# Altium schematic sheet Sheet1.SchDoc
size A4; SheetNumber: 3; SheetTotal: 4
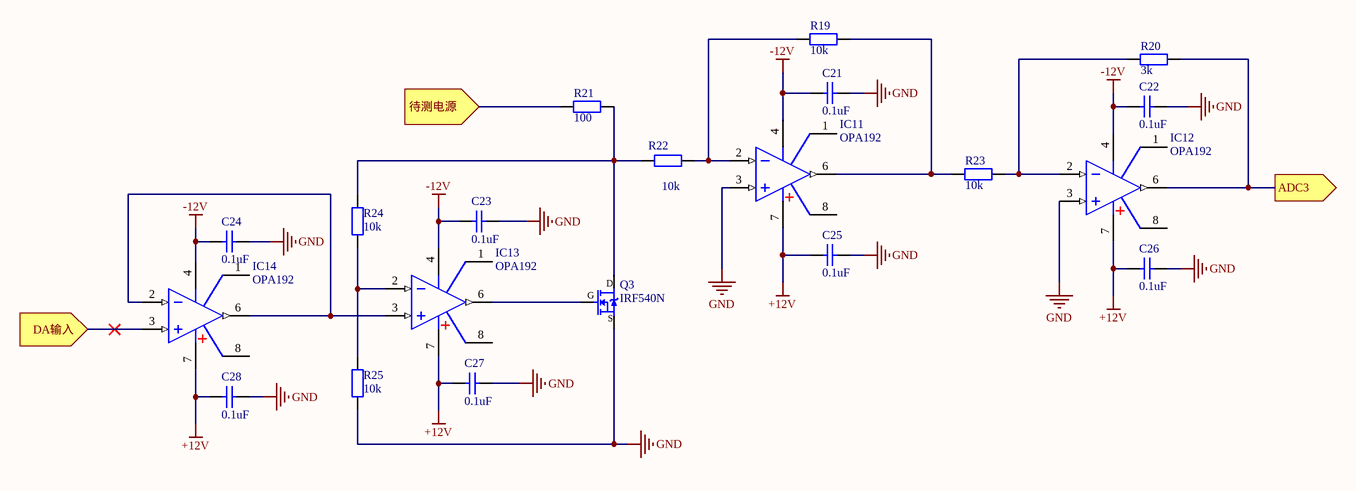
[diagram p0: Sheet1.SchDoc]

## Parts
C21  0.1uF  [瓷片电容]
C22  0.1uF  [瓷片电容]
C23  0.1uF  [瓷片电容]
C24  0.1uF  [瓷片电容]
C25  0.1uF  [瓷片电容]
C26  0.1uF  [瓷片电容]
C27  0.1uF  [瓷片电容]
C28  0.1uF  [瓷片电容]
IC11  OPA192  [SOP8_N]
IC12  OPA192  [SOP8_N]
IC13  OPA192  [SOP8_N]
IC14  OPA192  [SOP8_N]
Q3  IRF540N  [TO263-3B]
R19  10k  [RS 1/4W]
R20  3k  [RS 1/4W]
R21  100  [RS 1/4W]
R22  10k  [RS 1/4W]
R23  10k  [RS 1/4W]
R24  10k  [RS 1/4W]
R25  10k  [RS 1/4W]

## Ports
ADC3 (out), DA输入 (in), 待测电源 (in)

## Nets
+12V: C25.1 C26.1 C27.1 C28.1 IC11.7(V+) IC12.7(V+) IC13.7(V+) IC14.7(V+)
-12V: C21.1 C22.1 C23.1 C24.1 IC11.4(V-) IC12.4(V-) IC13.4(V-) IC14.4(V-)
GND: C21.2 C22.2 C23.2 C24.2 C25.2 C26.2 C27.2 C28.2 IC11.3(IN+) IC12.3(IN+) Q3.3(D) R25.1
ADC3: IC12.6(OUT) R20.2 ; port ADC3
DA输入: IC14.3(IN+) ; port DA输入
待测电源: R21.2 ; port 待测电源
NetIC11_2: IC11.2(IN-) R19.1 R22.2
NetIC11_6: IC11.6(OUT) R19.2 R23.1
NetIC12_2: IC12.2(IN-) R20.1 R23.2
NetIC13_2: IC13.2(IN-) R24.1 R25.2
NetIC13_3: IC13.3(IN+) IC14.2(IN-) IC14.6(OUT)
NetIC13_6: IC13.6(OUT) Q3.1(G)
NetQ3_2: Q3.2(S) R21.1 R22.1 R24.2

Not connected (* = marked no-connect by the designer): IC11 1 8; IC12 1 8; IC13 1 8; IC14 1 8

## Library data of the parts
C21-C28 = Cap_DIP: 直插电容; Value: 100nF; Voltage: 63V
IC11-IC14 = OPA192: High-Voltage, Rail-to-Rail Input/Output, 5µV, 0.2µV/˚C, Precision Operational Amplifier; BOM名称: 单路精密运放; 版权归属: 源创客
Q3 = IRF540N: N沟场 100V/22A; BOM名称: 效应管; 版权归属: 源创客
R19-R25 = Res_DIP: 直插电阻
